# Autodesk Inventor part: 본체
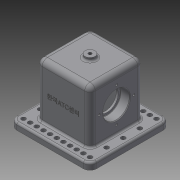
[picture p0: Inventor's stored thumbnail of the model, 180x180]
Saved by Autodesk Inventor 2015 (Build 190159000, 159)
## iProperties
Created: 2018-11
Part Number: 본체
Material: 일반
Document SubType Name: Modeling
Designer: now
Density: 1 g/cm^3
Appearance: 기본값
Author: now
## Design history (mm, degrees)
sketch "스케치1"
  geometry: L1 (-40, 40)-(40, 40); L2 (40, 40)-(40, -40); L3 (40, -40)-(-40, -40); L4 (-40, -40)-(-40, 40); L5 (-40, 40)-(40, -40); L6 (40, 40)-(-40, -40); 1 further point
  constraints: 12 end point, 2 midpoint, 2 parallel, 1 horizontal, 1 perpendicular
  dimensions: "d0" = 80 distance of L2.end L3.end; "d1" = 80 distance of L1.end L2.end
extrude "돌출1" new body sketch "스케치1" distance "d2" = 80; taper "d3" = 0 deg
fillet "모깎기1" dims "d4" = 8
sketch "스케치5"
  geometry: L1 (60, -60)-(-60, -60); L2 (-60, -60)-(-60, 60); L3 (-60, 60)-(60, 60); L4 (60, 60)-(60, -60); L5 (60, -60)-(-60, 60); L6 (-60, -60)-(60, 60); 1 further point
  constraints: 12 end point, 2 midpoint, 2 parallel, 1 horizontal, 1 perpendicular
  dimensions: "d15" = 120 distance of L3.end L1.start; "d16" = 120 distance of L2.end L3.end
extrude "돌출4" join sketch "스케치5" distance "d17" = 10; taper "d18" = 0 deg
sketch "스케치6"
  geometry: L1 (-23, -30)-(23, -30); L2 (23, -30)-(23, 30); L3 (23, 30)-(-23, 30); L4 (-23, 30)-(-23, -30); L5 (-23, -30)-(23, 30); L6 (23, -30)-(-23, 30); 1 further point
  constraints: 12 end point, 2 midpoint, 2 parallel, 1 horizontal, 1 perpendicular
  dimensions: "d19" = 46 distance of L1.start L1.end; "d20" = 60 distance of L1.end L2.end
extrude "돌출5" cut sketch "스케치6" distance "d21" = 80; taper "d22" = 0 deg
sketch "스케치8"
  geometry: L1 (80, 64)-(80, 0) reference; C1 r 16.5 at (42, 32); 2 further points
  constraints: 1 centre point, 1 horizontal alignment, 1 midpoint
  dimensions: "d23" = 33 diameter of C1; "d24" = 38 distance of point (80, 32) C1.centre
extrude "돌출6" cut sketch "스케치8" stored distance "d25" = 10; taper "d26" = 0 deg
sketch "스케치9"
  geometry: C1 r 16.5 at (42, 32) reference; C2 r 20 at (42, 32); 1 further point
  constraints: 1 centre point, 1 coincident
  dimensions: "d27" = 40 diameter of C2
extrude "돌출7" cut sketch "스케치9" distance "d28" = 14; taper "d29" = 0 deg
fillet "모깎기3" dims "d30" = 0.6
sketch "스케치10"
  geometry: L1 (80, 64)-(80, 0) reference; C1 r 20 at (42, 32) reference; 3 further points
  constraints: 1 horizontal alignment, 1 midpoint
  dimensions: "d31" = 26 distance of point (16, 32) C1.centre
hole "구멍1" sketch "스케치10" at (16, 32) diameter "d32" = 3.242; stored, may be unused: countersink angle "d36" = 90 deg, drill point angle "d38" = 118 deg; dims "d33" = 8, "d34" = 4, "d35" = 2, "d37" = 10
fillet "모깎기4" dims "d42" = 10
node "작업 평면2"
sketch "스케치11"
  geometry: C1 r 7.5 at (0, 0); 1 further point
  constraints: 1 centre point, 1 coincident
  dimensions: "d44" = 15 diameter of C1
extrude "돌출8" join sketch "스케치11" stored distance "d45" = 14; taper "d46" = 0 deg
fillet "모깎기5" dims "d47" = 8
sketch "스케치12"
  geometry: C1 r 7.5 at (0, 0) reference
hole "구멍2" sketch "스케치12" at (0, 0) diameter "d48" = 4.917; stored, may be unused: countersink angle "d52" = 90 deg, drill point angle "d54" = 118 deg; dims "d49" = 12, "d50" = 4, "d51" = 2, "d53" = 17.1
sketch "스케치13"
  geometry: C1 r 3.3 at (-50, -50); A1 r 10 centre (-50, -50) between (-60, -50) and (-50, -60) reference; 1 further point
  constraints: 1 centre point, 1 coincident
  dimensions: "d55" = 6.6 diameter of C1
extrude "돌출9" cut sketch "스케치13" stored distance "d56" = 14; taper "d57" = 0 deg
fillet "모깎기6" dims "d64" = 3
fillet "모깎기7" dims "d65" = 3
sketch "스케치14"
  geometry: L1 (92, -82)-(82, -82) reference; 2 further points
  constraints: 1 vertical alignment, 1 other
  dimensions: "d66" = 48 distance from line of L1 point (32, -34)
feature "엠보싱1" sketch "스케치14" dims "d0" = 80, "d1" = 80, "d67" = 0.5, "d68" = 0
fillet "모깎기8" dims "d69" = 3
fillet "모깎기9" dims "d70" = 3
chamfer "모따기1" distance "d71" = 1; stored, may be unused: second distance "d72" = 2, angle "d73" = 45 deg
node "솔리드1"
mirror "대칭1"
pattern_circular "원형 패턴1" dims angle "d40" = 360 deg
mirror "대칭2"
pattern_linear "직사각형 패턴1" dims "d60" = 10
mirror "대칭3"
pattern_linear "직사각형 패턴2" dims "d63" = 25
mirror "대칭4"
other parameters: "d43" = -95
